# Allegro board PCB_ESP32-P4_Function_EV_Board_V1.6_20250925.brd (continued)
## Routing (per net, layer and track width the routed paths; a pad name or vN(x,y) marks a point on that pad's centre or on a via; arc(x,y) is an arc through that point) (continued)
GND_EARTH: length 183
  TOP w0.635: 35.35,6.15 J19.18 36.13,4.82 ; J18.6 16.55,11.71 ; J18.6 18.63,9.63 ; J18.6 14.47,9.63 ; J18.6 16.55,7.55 ; 29.74,4.82 J15.19 30.52,6.15 ; 20.31,1.97 J15.17 ; J15.17 21.09,3.15 ; J15.17 21.87,1.97 ; J20.17 51.17,3.15 ; J20.17 50.39,1.97 ; J20.17 51.95,1.97 ; 21.09,4.82 J15.18 20.31,6.15 ; 35.35,1.97 J19.17 ; J19.17 36.91,1.97 ; J19.17 36.13,3.15 ; 45.56,6.15 J19.19 44.78,4.82 ; 51.17,4.82 J20.18 50.39,6.15 ; 59.04,1.97 J20.20 ; J20.20 59.82,3.15 ; J20.20 60.6,1.97 ; 3.41,7.55 J18.5 ; J18.5 1.33,9.63 ; J18.5 3.41,11.71 ; J18.5 5.49,9.63 ; 44,1.97 J19.20 ; J19.20 45.56,1.97 ; J19.20 44.78,3.15 ; 60.6,6.15 J20.19 59.82,4.82 ; 28.96,1.97 J15.20 ; J15.20 30.52,1.97 ; J15.20 29.74,3.15
  GND w0.635: 44,1.97 J19.20 ; J19.20 45.56,1.97 ; J19.20 44.78,3.15 ; J15.17 21.87,1.97 ; J15.17 20.31,1.97 ; J15.17 21.09,3.15 ; J19.17 36.91,1.97 ; J19.17 35.35,1.97 ; J19.17 36.13,3.15 ; J18.5 5.49,9.63 ; J18.5 1.33,9.63 ; J18.5 3.41,7.55 ; J18.5 3.41,11.71 ; J20.17 51.95,1.97 ; J20.17 51.17,3.15 ; J20.17 50.39,1.97 ; 14.47,9.63 J18.6 ; J18.6 16.55,7.55 ; J18.6 18.63,9.63 ; J18.6 16.55,11.71 ; J20.20 59.82,3.15 ; J20.20 60.6,1.97 ; J20.20 59.04,1.97 ; 44.78,4.82 J19.19 45.56,6.15 ; 20.31,6.15 J15.18 21.09,4.82 ; 36.13,4.82 J19.18 35.35,6.15 ; 28.96,1.97 J15.20 ; J15.20 29.74,3.15 ; J15.20 30.52,1.97 ; 59.82,4.82 J20.19 60.6,6.15 ; 51.17,4.82 J20.18 50.39,6.15 ; 29.74,4.82 J15.19 30.52,6.15
  POWER w0.635: J15.20 30.52,1.97 ; J15.20 29.74,3.15 ; J15.20 28.96,1.97 ; J15.17 21.09,3.15 ; J15.17 20.31,1.97 ; J15.17 21.87,1.97 ; J18.5 3.41,11.71 ; J18.5 1.33,9.63 ; J18.5 5.49,9.63 ; J18.5 3.41,7.55 ; 59.82,4.82 J20.19 60.6,6.15 ; 59.04,1.97 J20.20 ; J20.20 60.6,1.97 ; J20.20 59.82,3.15 ; J19.17 36.91,1.97 ; J19.17 36.13,3.15 ; J19.17 35.35,1.97 ; 16.55,7.55 J18.6 ; J18.6 18.63,9.63 ; J18.6 16.55,11.71 ; J18.6 14.47,9.63 ; 45.56,6.15 J19.19 44.78,4.82 ; 50.39,1.97 J20.17 ; J20.17 51.17,3.15 ; J20.17 51.95,1.97 ; 20.31,6.15 J15.18 21.09,4.82 ; 30.52,6.15 J15.19 29.74,4.82 ; 51.17,4.82 J20.18 50.39,6.15 ; J19.20 44.78,3.15 ; J19.20 44,1.97 ; J19.20 45.56,1.97 ; 35.35,6.15 J19.18 36.13,4.82
  BOTTOM w0.635: 35.35,1.97 J19.17 ; J19.17 36.13,3.15 ; J19.17 36.91,1.97 ; 59.04,1.97 J20.20 ; J20.20 60.6,1.97 ; J20.20 59.82,3.15 ; 21.09,4.82 J15.18 20.31,6.15 ; J18.6 16.55,11.71 ; J18.6 16.55,7.55 ; J18.6 18.63,9.63 ; J18.6 14.47,9.63 ; 51.17,4.82 J20.18 50.39,6.15 ; J19.20 45.56,1.97 ; J19.20 44.78,3.15 ; J19.20 44,1.97 ; 29.74,4.82 J15.19 30.52,6.15 ; J15.17 21.09,3.15 ; J15.17 20.31,1.97 ; J15.17 21.87,1.97 ; 36.13,4.82 J19.18 35.35,6.15 ; 60.6,6.15 J20.19 59.82,4.82 ; 1.33,9.63 J18.5 ; J18.5 5.49,9.63 ; J18.5 3.41,11.71 ; J18.5 3.41,7.55 ; 50.39,1.97 J20.17 ; J20.17 51.95,1.97 ; J20.17 51.17,3.15 ; 28.96,1.97 J15.20 ; J15.20 29.74,3.15 ; J15.20 30.52,1.97 ; 44.78,4.82 J19.19 45.56,6.15
  vias: v1(0.82,11.81) v1(0.88,8.55) v1(0.92,4.63) v1(1.45,1.17) v1(3.47,6.29) v1(3.53,2.97) v1(3.94,11.86) v1(5.96,9.74) v1(6.47,4.71) v1(6.56,0.97) v1(8.63,9.17) v1(9.34,6.52) v1(9.39,2.86) v1(11.56,4.8) v1(11.65,0.9) v1(11.92,9.17) v1(13.9,6.68) v1(13.86,2.96) v1(14.14,10.02) v1(16.14,4.91) v1(16.18,0.96) v1(18.41,6.71) v1(18.37,2.97) v1(18.89,9.15) v1(20.26,0.85) v1(20.44,7.56) v1(21.1,4.44) v1(21.07,3.45) v1(22.6,3.01) v1(23.23,0.9) v1(25.33,3.03) v1(27.02,0.9) v1(28.08,3.01) v1(29.76,4.41) v1(29.76,3.45) v1(30.7,0.83) v1(30.84,6.92) v1(32.79,5.13) v1(32.82,2.59) v1(35.09,6.98) v1(35.17,0.87) v1(36.13,4.46) v1(36.13,3.4) v1(37.27,0.88) v1(37.67,3.09) v1(40.55,2.01) v1(43.5,3.01) v1(43.62,0.86) v1(44.79,4.46) v1(44.79,3.42) v1(45.65,0.88) v1(45.99,6.92) v1(47.98,5.11) v1(48,2.54) v1(50.04,6.92) v1(50.24,0.86) v1(51.18,4.44) v1(51.18,3.47) v1(52.92,3) v1(52.93,0.91) v1(55.73,2.07) v1(58.27,3.04) v1(58.32,0.91) v1(59.82,4.44) v1(59.84,3.42) v1(60.85,7.1) v1(61.01,1.93) v1(61.7,7.11) v1(61.74,3.85) v1(62.12,5.96) v1(62.96,5.91) v1(63.73,7.1) v1(63.68,3.89) v1(63.71,0.93)
GND_RJ45_EARTH: length 18.6
  TOP w1.2: R181.1 84.39,11.83 J17.SHD1 J17.SHD2
VBUS_EN: length 2.7
  TOP w0.254: R145.2 17.17,24.14 16.25,23.23 R152.2 U9.4
VBUS_OUT: length 26.5
  TOP w0.635: 5.49,12.34 J18.1 ; J18.1 6.48,13.33 ; J18.1 7.47,12.34 ; J18.1 6.48,11.35
  TOP w0.8: U9.1 18.88,20.14 18.51,19.77
  TOP w1: C75.1 C72.1 16.77,18.03 18.51,19.77
  POWER w1: v1(19.98,16.25) v1(19.27,16.25) 13.66,16.25 11.17,18.74 8.3,18.74 v1(6.57,17.01) v1(6.57,16.35)
VCC_5V: length 164.8
  TOP w0.254: v1(43.68,18.02) 43.34,18.02 C71.1 ; R226.2 53.64,39.92 52.9,39.18 51.44,39.18 v1(50.86,39.77) ; R175.2 41.22,18.48 41.21,18.48 ; R173.1 v1(49.68,14.49) ; R151.1 18.28,23.26 R145.1 18.28,24.52 v1(18.03,24.78)
  TOP w0.508: U5.1 50.83,41.88 C48.1 50.84,40.59 C49.1 v1(50.86,39.77)
  TOP w0.8: 57.74,41.71 58.03,42 v1(58.03,42.08) v1(57.37,42.08) 57.37,42.08 57.74,41.71 ; 57.74,41.71 57.74,41.27 R171.2
  TOP w1: 14.6,19.66 15.09,20.14 U9.5
  TOP w1.5: C71.1 38.22,18.48 SW3.1
  POWER w0.254: v1(49.68,14.49) 49.23,14.04 45.43,14.04 44.57,14.9 44.57,17.14 v1(43.68,18.02)
  POWER w0.508: 55.08,38.95 55.08,38.95 51.67,38.95 v1(50.86,39.77) ; J1.4 J1.2 6.85,70.25 6.85,68.1 1.44,62.69 1.44,32.3 13.71,20.03
  POWER w0.8: 55.08,38.95 55.08,39.79 v1(57.37,42.08)
  POWER w1: 14.14,19.7 21.7,19.7 22.67,20.66 45.02,20.66 55.08,30.72 55.08,38.95
  POWER w1.5: 37.1,20.66 37.1,20.66 SW3.1
  BOTTOM w0.254: v1(18.03,24.78) 13.71,20.46 v1(13.71,20.1)
  vias: v1(13.71,19.44)
VDD_FLASH: length 16
  TOP w0.18: 18.1,45.66 18.1,45.51 18.71,44.9 18.84,44.9 18.91,44.83 U4.30
  TOP w0.381: U2.8 15.43,58.15 15.81,57.77 15.81,56.85 15.74,56.77 C16.1 R18.2 15.74,54.51 16.68,53.57 R35.2 R37.2 C20.1 C25.1 16.68,47.08 18.1,45.66
25M_XI: length 1.3
  TOP w0.127: R161.1 74.42,24.46 U8.2
25M_XO: length 1.3
  TOP w0.127: R158.1 74.45,24.86 U8.3
ADCVREF: length 14.8
  TOP w0.254: U3.15 67.82,52.2 68.21,52.59 68.21,53.13 68.57,53.48 C43.1 69.02,55.85 66.77,58.11 60.95,58.11 R73.2
BAT: length 2.3
  BOTTOM w0.381: TP2.1 30.24,49.44 R196.1
C6_EN: length 59.7
  TOP w0.127: U1.8 75.3,70.84 R4.1 C8.1 72.54,72.66 68.11,72.66 J2.1 ; v1(49.9,59.55) 44.72,59.55 38.75,53.58 38.75,43.37 R76.2
  POWER w0.127: J2.1 65.04,69.59 v1(65.04,66.87)
  BOTTOM w0.127: v1(65.04,66.87) 63.64,65.47 55.82,65.47 v1(49.9,59.55)
C6_IO8: length 1.7
  TOP w0.127: U1.22 R10.1
C6_IO9: length 10.3
  TOP w0.127: v1(73.31,65.17) 73.31,61.03 72.67,60.38 U1.23
  BOTTOM w0.127: v1(73.31,65.17) 72.49,65.99 J2.6
C6_U0RXD: length 14
  TOP w0.127: v1(76.89,59.35) 76.9,59.34 U1.30
  BOTTOM w0.127: J2.5 68.11,64.4 71.06,64.4 76.11,59.35 v1(76.89,59.35)
C6_U0TXD: length 17.3
  TOP w0.127: v1(77.7,59.86) U1.31
  BOTTOM w0.127: v1(77.7,59.86) 76.08,59.86 71.2,64.73 68.32,64.73 67.81,65.24 67.81,67.24 J2.3
C6_WAKEUP: length 59.3
  TOP w0.127: v1(77.71,68.27) 77.7,68.28 U1.5 ; v1(52.21,60.49) 34.18,60.49 29.76,56.07 R30.2
  POWER w0.127: v1(77.71,68.27) 72.38,62.93 64.47,62.93 62.28,65.12 56.84,65.12 v1(52.21,60.49)
CNN_GPIO0: length 28
  BOTTOM w0.127: R199.1 32.1,47.08 36.26,47.08 37.81,48.63 37.81,64.94 36.31,66.44 J1.23
CNN_GPIO1: length 30.9
  BOTTOM w0.127: R197.1 32.12,47.39 36.08,47.39 37.43,48.73 37.43,64.53 35.04,66.92 35.04,70.5 J1.22
CNN_GPIO2: length 16.6
  TOP w0.127: R22.1 31.48,55.71 v1(31.87,56.1)
  BOTTOM w0.127: J1.21 31.87,67.33 v1(31.87,56.1)
CNN_GPIO3: length 18.5
  TOP w0.127: R48.1 30.39,51.6 v1(30.67,51.88)
  BOTTOM w0.127: J1.19 31.38,69.08 31.38,55.69 30.67,54.98 v1(30.67,51.88)
CNN_GPIO4: length 19
  TOP w0.127: R31.1 v1(30.62,56.12)
  BOTTOM w0.127: v1(30.62,56.12) 30.39,56.35 30.39,66.75 29.96,67.19 29.96,70.5 J1.18
CNN_GPIO5: length 21.9
  TOP w0.127: R47.1 v1(29.35,51.88)
  BOTTOM w0.127: J1.16 27.42,70.5 27.42,68.62 29.4,66.64 29.4,51.93 v1(29.35,51.88)
CNN_GPIO6: length 16.8
  TOP w0.127: v1(28.89,56.17) 28.89,54.52 28.89,54.52 R29.1
  BOTTOM w0.127: J1.15 28.89,66.49 v1(28.89,56.17)
CNN_GPIO7: length 32.5
  TOP w0.127: R46.1 28.31,51.78 v1(28.44,51.91) ; v1(27.32,65.1) 15.04,65.1 J1.3
  BOTTOM w0.127: v1(27.32,65.1) 27.32,57.06 28.44,55.95 v1(28.44,51.91)
CNN_GPIO8: length 27.3
  TOP w0.127: v1(27.78,55.92) R28.1 ; v1(26.86,65.56) 17.12,65.56 J1.5
  BOTTOM w0.127: v1(26.86,65.56) 26.86,56.83 v1(27.78,55.92)
CNN_GPIO20: length 16.5
  TOP w0.127: R33.1 v1(21.48,54.27)
  BOTTOM w0.127: J1.13 21.48,67.1 v1(21.48,54.27)
CNN_GPIO21: length 18.1
  TOP w0.127: R39.1 v1(20.97,51.88)
  BOTTOM w0.127: J1.11 20.97,69.13 v1(20.97,51.88)
CNN_GPIO22: length 18.9
  TOP w0.127: R32.1 v1(20.44,54.3)
  BOTTOM w0.127: J1.12 19.8,70.5 19.8,67.29 20.44,66.65 v1(20.44,54.3)
CNN_GPIO23: length 19.7
  TOP w0.127: R38.1 v1(19.93,51.88)
  BOTTOM w0.127: J1.7 19.93,65.29 v1(19.93,51.88)
CNN_GPIO26: length 64.4
  POWER w0.127: v1(17.11,26.55) 25.99,26.55 v1(26.69,27.24)
  BOTTOM w0.127: J1.31 46.47,66.64 40.38,60.54 40.38,41.93 34.79,36.34 34.79,34.98 28.88,29.07 28.35,29.07 26.69,27.41 v1(26.69,27.24) ; v1(17.11,26.55) 18.57,26.55 19.64,27.61 19.64,28.31 R228.2
CNN_GPIO27: length 75.9
  POWER w0.127: v1(17.39,25.95) 26.09,25.95 27.33,27.19 v1(27.33,27.3)
  BOTTOM w0.127: J1.38 52.9,72.96 48.48,72.96 47.73,72.22 47.73,67.26 40.74,60.28 40.74,41.86 35.11,36.22 35.11,34.8 29.05,28.74 28.46,28.74 27.33,27.61 v1(27.33,27.3) ; v1(17.39,25.95) 18.49,25.95 19.94,27.4 19.94,28.34 R227.2
CNN_GPIO32: length 52.9
  TOP w0.127: R116.2 v1(23.13,30.8)
  BOTTOM w0.127: v1(23.13,30.8) 24.54,30.8 25.05,30.29 28.41,30.29 33.52,35.4 33.52,37.63 33.57,37.68 33.57,37.73 38.55,42.71 38.55,66.75 40.12,68.33 40.12,70.5 J1.26
CNN_GPIO33: length 53.3
  TOP w0.127: R134.2 23.64,27.67 v1(24.15,27.17)
  BOTTOM w0.127: v1(24.15,27.17) 25.95,27.17 28.18,29.4 28.74,29.4 34.46,35.12 34.46,37.38 39.61,42.54 39.61,61.18 43.93,65.49 J1.29
CNN_GPIO36: length 49.6
  TOP w0.127: R112.2 v1(25.29,30.75)
  BOTTOM w0.127: v1(25.29,30.75) 28.44,30.75 33.21,35.52 33.21,37.71 33.32,37.81 33.32,37.86 38.19,42.74 38.19,65.29 37.58,65.9 37.58,70.5 J1.24
CNN_GPIO37: length 71.1
  TOP w0.127: R136.2 26.23,28.13 v1(26.23,28.13) ; J1.8 17.29,70.47 17.29,68.15 19.37,66.07 38,66.07 38.9,65.17 v1(39.39,65.17)
  BOTTOM w0.127: v1(39.39,65.17) 39.23,65.01 39.23,42.54 34.1,37.4 34.1,35.17 28.64,29.71 27.81,29.71 v1(26.23,28.13)
CNN_GPIO38: length 68.2
  TOP w0.127: v1(26.66,29.81) 26.28,30.19 R118.2 ; J1.10 19.78,70.52 19.78,68 21.37,66.41 38.4,66.41 v1(39.04,65.76)
  BOTTOM w0.127: v1(26.66,29.81) 26.85,30 28.53,30 33.82,35.3 33.82,37.61 38.93,42.71 38.93,65.65 v1(39.04,65.76)
CNN_GPIO45: length 43.3
  BOTTOM w0.127: R100.2 42.43,36.86 42.43,58.65 51.03,67.25 53.9,67.25 55.36,68.71 55.36,70.5 J1.40
CNN_GPIO46: length 42.3
  TOP w0.127: R97.2 v1(37.84,35.73)
  BOTTOM w0.127: J1.36 50.28,70.5 50.28,68.48 41.43,59.63 41.43,41.68 39.31,39.56 39.31,37.53 38.03,36.25 38.03,35.92 v1(37.84,35.73)
CNN_GPIO47: length 40.5
  TOP w0.127: R94.2 40.69,36.26 v1(41.79,37.35)
  BOTTOM w0.127: J1.37 52.45,67.59 50.69,67.59 42.13,59.03 42.13,37.94 41.79,37.59 v1(41.79,37.35)
CNN_GPIO48: length 37.7
  TOP w0.127: R93.2 v1(37.89,36.77)
  BOTTOM w0.127: J1.33 49.01,67.91 41.09,59.98 41.09,41.74 38.87,39.51 38.87,37.75 v1(37.89,36.77)
CNN_GPIO53: length 35.2
  TOP w0.127: R85.1 40.64,39.41 v1(41.39,40.16)
  BOTTOM w0.127: v1(41.39,40.16) 41.77,40.54 41.77,59.32 51.55,69.1 J1.35
CNN_GPIO54: length 35.9
  TOP w0.127: R80.1 37.68,39.92 v1(37.94,40.17)
  BOTTOM w0.127: J1.32 45.2,70.5 45.2,66.11 40,60.9 40,42.23 v1(37.94,40.17)
CODEC_CE: length 3.1
  TOP w0.127: U3.20 64.97,53.19 63.64,54.52 R60.1 R57.2
COL: length 3.4
  TOP w0.127: U8.4 73.96,25.26 75.15,26.45 R153.1 75.64,26.98 75.64,27.18 R149.2
CRS: length 5.2
  TOP w0.127: U8.20 68.06,25.66 R155.2 66.99,25.77 65.63,25.77 65.32,26.08 65.32,26.27 R154.1
CSI_A_CLKN: length 23.5
  TOP w0.102: R86.2 16.41,39.19 14.32,39.19 12.83,37.69 12.83,36.06 13.06,35.83 14.53,35.83 14.8,35.56 14.8,34.88 14.92,34.76 15.66,34.76 15.95,34.47 15.95,34.07 15.68,33.8 14.92,33.8 14.8,33.68 14.8,33.51 14.92,33.39 15.61,33.39 15.92,33.08 15.92,32.69 15.65,32.43 14.9,32.43 14.8,32.32 14.8,31.77 14.52,31.49 14.09,31.49 13.81,31.77 13.81,34.58 13.68,34.71 13.32,34.71 13.2,34.59 13.2,33.84 12.93,33.57 12.08,33.57 11.75,33.23 J9.8
CSI_A_CLKP: length 23.5
  TOP w0.102: J9.9 11.77,34.23 12.16,33.85 12.82,33.85 12.92,33.95 12.92,34.71 13.2,34.99 13.79,34.99 14.09,34.7 14.09,31.88 14.2,31.77 14.4,31.77 14.52,31.88 14.52,32.44 14.78,32.7 15.54,32.7 15.64,32.81 15.64,32.97 15.49,33.11 14.8,33.11 14.52,33.39 14.52,33.79 14.8,34.08 15.57,34.08 15.68,34.18 15.68,34.35 15.54,34.48 14.8,34.48 14.52,34.77 14.52,35.45 14.42,35.55 12.94,35.55 12.55,35.94 12.55,37.81 14.2,39.46 16.41,39.46 R82.2
CSI_A_DATA0N: length 22.3
  TOP w0.102: J9.2 10.43,27.23 10.18,27.49 9.63,27.49 8.77,28.34 8.77,40.74 9.43,41.39 12.49,41.39 13.45,40.43 15.08,40.43 R78.2
CSI_A_DATA0P: length 22.3
  TOP w0.102: J9.3 10.48,28.23 10.02,27.77 9.74,27.77 9.61,27.89 9.61,28.06 9.49,28.19 9.32,28.19 9.05,28.46 9.05,28.64 9.22,28.82 9.22,29.01 9.05,29.18 9.05,29.38 9.25,29.58 9.25,29.78 9.05,29.98 9.05,30.21 9.25,30.41 9.25,30.62 9.05,30.82 9.05,31.11 9.25,31.31 9.25,31.51 9.05,31.71 9.05,40.62 9.54,41.11 12.37,41.11 13.33,40.15 15,40.15 15.2,39.95 R81.2
CSI_A_DATA1N: length 18.9
  TOP w0.102: v1(14.34,30.06) 14.34,30.33 14.18,30.5 12,30.5 11.74,30.23 J9.5 ; R88.2 15.08,38.53 14.75,38.53 14.33,38.12 14.33,36.96 v1(14.14,36.77)
  BOTTOM w0.102: v1(14.34,30.06) 14.34,31.96 14.22,32.08 11.46,32.08 11.18,32.36 11.18,32.76 11.46,33.04 14.22,33.04 14.34,33.16 14.34,36.57 v1(14.14,36.77)
CSI_A_DATA1P: length 18.8
  TOP w0.102: v1(14.82,36.77) 14.72,36.77 14.61,36.88 14.61,38 14.86,38.25 15,38.25 15.2,38.06 R90.2 ; J9.6 11.76,31.23 12.22,30.77 14.29,30.77 14.6,30.46 14.75,30.46 v1(14.83,30.54)
  BOTTOM w0.102: v1(14.83,30.54) 14.72,30.54 14.62,30.64 14.62,32.08 14.34,32.36 11.58,32.36 11.46,32.48 11.46,32.65 11.58,32.76 14.34,32.76 14.62,33.05 14.62,35.83 14.8,36.01 14.8,36.22 14.62,36.4 14.62,36.67 14.72,36.77 v1(14.82,36.77)
CSI_CLKN: length 2.4
  TOP w0.102: U4.45 19,39.58 18.97,39.61 18.07,39.61 17.65,39.19 17.29,39.19 R86.1
CSI_CLKP: length 2.4
  TOP w0.102: U4.44 19,39.92 18.96,39.89 17.96,39.89 17.53,39.46 17.29,39.46 R82.1
CSI_DATA0N: length 3.8
  TOP w0.102: R78.1 15.89,40.36 16.26,40.36 16.49,40.59 18.97,40.59 19.01,40.62 U4.42
CSI_DATA0P: length 3.8
  TOP w0.102: R81.1 15.89,40.09 16.38,40.09 16.6,40.31 18.98,40.31 19.01,40.27 U4.43
CSI_DATA1N: length 4
  TOP w0.102: U4.46 18.98,39.23 18.95,39.19 18.29,39.19 17.56,38.46 15.89,38.46 R88.1
CSI_DATA1P: length 4
  TOP w0.102: U4.47 18.99,38.88 18.96,38.91 18.4,38.91 17.68,38.19 15.89,38.19 R90.1
CSI_IO0: length 3.5
  TOP w0.127: J9.11 v1(9.87,36.23)
  BOTTOM w0.127: v1(9.87,36.23) 9.54,36.23 R123.2
CSI_IO1: length 3.6
  TOP w0.127: J9.12 v1(9.87,37.23)
  BOTTOM w0.127: R111.2 9.67,37.23 v1(9.87,37.23)
CSI_REXT: length 1.4
  TOP w0.18: U4.48 v1(19.93,38.52)
  BOTTOM w0.18: v1(19.93,38.52) 19.93,38.73 R203.1
DACVREF: length 2.1
  TOP w0.254: C42.2 68.9,52.57 68.13,51.8 U3.14
DSI_A_CLKN: length 24.6
  TOP w0.102: J5.5 4.8,51.5 4.32,51.98 3.97,51.98 3.85,51.85 3.85,51.72 3.72,51.59 3.59,51.59 3.47,51.48 3.47,51.25 3.69,51.04 3.69,50.8 3.47,50.59 3.47,50.34 3.67,50.15 3.67,49.9 3.47,49.7 3.47,49.51 3.67,49.31 3.67,49.04 3.47,48.85 3.47,48.62 3.69,48.4 3.69,48.23 3.47,48.01 3.47,47.34 4.11,46.7 8.88,46.7 9,46.82 9,47.78 9.28,48.06 9.68,48.06 9.96,47.78 9.96,46.82 10.08,46.7 10.96,46.7 11.23,46.44 11.23,45.98 10.87,45.63 10.87,45.46 10.99,45.34 11.16,45.34 11.51,45.69 11.91,45.69 14.88,42.72 15.03,42.72 15.2,42.89 R72.1
DSI_A_CLKP: length 24.6
  TOP w0.102: R74.1 15.06,42.44 14.77,42.44 11.8,45.41 11.63,45.41 11.28,45.06 10.88,45.06 10.59,45.34 10.59,45.74 10.95,46.1 10.95,46.32 10.85,46.42 9.96,46.42 9.68,46.7 9.68,47.66 9.56,47.78 9.39,47.78 9.28,47.66 9.28,46.7 8.99,46.42 3.99,46.42 3.2,47.22 3.2,51.59 3.86,52.26 4.51,52.26 4.75,52.5 J5.6
DSI_A_DATA0N: length 23
  TOP w0.102: v1(7.86,45.31) 8.07,45.1 8.07,44.65 8.69,44.03 11.18,44.03 13.73,41.49 16.41,41.49 R77.1 ; v1(7.25,54.66) 7.05,54.86 6.42,54.86 6.06,54.5 J5.8
  BOTTOM w0.102: v1(7.25,54.66) 7.45,54.85 7.69,54.85 8.07,54.46 8.07,45.53 v1(7.86,45.31)
DSI_A_DATA0P: length 23
  TOP w0.102: R75.1 16.41,41.76 13.84,41.76 11.29,44.31 8.8,44.31 8.35,44.76 8.35,45.12 v1(8.54,45.31) ; v1(7.25,55.34) 7.05,55.14 6.45,55.14 6.09,55.5 J5.9
  BOTTOM w0.102: v1(7.25,55.34) 7.46,55.13 7.8,55.13 8.35,54.58 8.35,45.49 8.53,45.31 v1(8.54,45.31)
DSI_A_DATA1N: length 26
  TOP w0.102: J5.2 6.04,48.5 6.4,48.86 8.78,48.86 9.19,49.27 9.19,52.92 9.32,53.05 9.49,53.05 9.6,52.94 9.6,52.3 9.88,52.01 10.88,52.01 10.99,51.91 10.99,51.74 10.86,51.61 9.88,51.61 9.6,51.32 9.6,50.92 9.88,50.64 10.83,50.64 10.95,50.52 10.95,50.35 10.83,50.23 9.88,50.23 9.6,49.95 9.6,49.21 9.96,48.85 10.51,48.85 15.92,43.44 16.41,43.44 R71.1
DSI_A_DATA1P: length 26
  TOP w0.102: J5.3 6.06,49.5 6.42,49.14 8.66,49.14 8.91,49.39 8.91,53.03 9.21,53.33 9.61,53.33 9.88,53.06 9.88,52.41 10,52.29 11,52.29 11.27,52.02 11.27,51.62 10.97,51.33 10,51.33 9.88,51.21 9.88,51.04 10,50.92 10.95,50.92 11.23,50.64 11.23,50.24 10.95,49.96 10,49.96 9.88,49.84 9.88,49.32 10.08,49.13 10.62,49.13 16.03,43.71 16.41,43.71 R69.1
DSI_CLKN: length 3.8
  TOP w0.102: R72.2 15.89,42.76 17.52,42.76 17.94,42.34 18.97,42.34 19.01,42.38 U4.37
DSI_CLKP: length 3.8
  TOP w0.102: R74.2 15.89,42.49 17.4,42.49 17.82,42.06 18.98,42.06 19.02,42.02 U4.38
DSI_DATA0N: length 2.3
  TOP w0.102: U4.40 18.98,41.33 18.95,41.36 17.74,41.36 17.61,41.49 17.29,41.49 R77.2
DSI_DATA0P: length 2.3
  TOP w0.102: R75.2 17.29,41.76 17.73,41.76 17.85,41.64 18.96,41.64 18.99,41.67 U4.39
DSI_DATA1N: length 2.5
  TOP w0.102: U4.36 19,42.73 18.97,42.76 18.06,42.76 17.4,43.42 17.27,43.42 R71.2
DSI_DATA1P: length 2.5
  TOP w0.102: R69.2 17.3,43.7 17.52,43.7 18.18,43.04 18.96,43.04 19,43.08 U4.35
DSI_REXT: length 1.3
  TOP w0.18: U4.34 v1(19.9,43.42)
  BOTTOM w0.18: R202.1 19.9,43.24 v1(19.9,43.42)
EN_DCDC: length 9.8
  TOP w0.127: v1(29.53,35.78) 29.28,36.03 29.28,36.63 29.44,36.79 29.44,37.01 29.33,37.12 U4.79 ; U7.1 31.11,29.51 v1(31.11,29.51)
  POWER w0.127: v1(29.53,35.78) 29.7,35.78 30.22,35.26 30.22,30.4 v1(31.11,29.51)
ESP_3V3: length 349.5
  TOP w0.18: v1(28.16,37.23) 28.23,37.16 U4.77 ; U4.75 27.52,37.2 v1(27.5,37.23) ; U4.96 v1(28.49,43.08) ; v1(28.44,44.62) 28.65,44.83 U4.101 ; 22.98,36.58 v1(22.98,37.2) ; v1(25.49,45.68) 25.77,45.97 U4.9 ; U4.21 v1(21.57,45.76)
  TOP w0.254: R60.2 v1(63.59,56.15) ; R3.1 76.73,56.23 76.68,56.18 ; 74.8,56.18 72.38,56.18 71.8,56.76 R6.1 70.65,56.87 R12.1 R11.1 R10.2 69.31,63.77 v1(69.29,63.78) ; 74.8,56.18 76.68,56.18 ; 74.8,56.18 74.77,56.21 R5.1 ; 76.68,56.18 78.15,56.18 78.71,56.74 R1.1 ; R4.2 75.69,71.47 77.34,71.47 C1.1
  TOP w0.381: R51.1 60.42,49.77 v1(59.73,50.46) ; R35.1 v1(15.66,52.57)
  TOP w0.508: 6.85,61.02 6.37,61.5 J5.15 ; 6.85,61.02 6.9,60.97 C10.1 7.69,62.26 C7.1 v1(7.68,63.16) ; 6.85,61.02 6.33,60.5 J5.14 ; J9.15 v1(9.87,40.23)
  TOP w0.635: C2.1 79.3,71.86 U1.3 ; R127.1 v1(39.42,29.91)
  POWER w0.254: v1(8.13,42.48) 8.13,41.1 5.73,38.7 v1(5.73,35.71)
  POWER w0.508: v1(8.13,42.48) 6.67,42.48 2.71,46.45 2.71,56.2 4.05,57.55 7.68,57.55 ; 7.68,57.55 7.74,57.55 ; 7.68,57.55 v1(7.68,63.16)
  POWER w0.635: v1(53.53,66.06) 53.64,66.16 63.21,66.16 65.59,63.78 v1(69.29,63.78) 70.21,63.78 v1(78.94,72.51) v1(79.6,72.51) ; J1.1 8.37,68.45 9.81,67.01 28.74,67.01 28.69,67.06 J1.17
  POWER w0.8: 7.74,57.55 12.72,52.57 v1(15.66,52.57) 21.28,46.95 21.28,46.27
  POWER w1: 28.74,67.01 51.18,67.01 52.3,65.89 53.14,65.89 ; 27.8,37.79 30.52,37.79 38.4,29.91 v1(39.42,29.91)
  POWER w1.2: v1(39.42,29.91) 43.31,26.03 46.19,26.03
  BOTTOM w0.127: Q8.2 60.23,35.75 R230.2 ; R209.2 20.69,36.74 v1(21.25,37.3)
  BOTTOM w0.254: R123.1 7.13,35.71 R111.1 ; R208.2 22.62,28.29 22.62,26.61 25.29,23.94 43.68,23.94 v1(45.66,25.92) ; R111.1 7.13,35.73 R109.1 ; R111.1 v1(5.73,35.71) ; v1(23.74,37.33) 23.74,37.44 23.27,37.91 R233.2 ; R98.1 C47.1 ; v1(63.59,56.15) 63.59,53.46 60.59,50.46 v1(59.73,50.46)
  BOTTOM w0.381: C90.1 28.52,43.04 v1(28.49,43.08) ; R198.1 26.58,47.11 25.49,46.02 v1(25.49,45.68) C83.1 C87.1 ; v1(22.98,37.2) 22.63,36.86 22.63,36.59 C97.1 ; 47.26,50.43 47.39,50.56 59.63,50.56 v1(59.73,50.46) ; Q8.2 61.74,34.93 61.74,33.23 60.77,32.26 ; v1(21.57,45.76) 21.58,45.76 C88.1 ; v1(28.44,44.62) C85.1
  BOTTOM w0.508: v1(8.13,42.48) C46.1 8.14,41.61 C47.1 9.83,40.27 v1(9.87,40.23) ; 60.77,32.26 62.25,30.79 64.6,30.79 R213.1
  BOTTOM w0.8: 47.26,38.6 49.49,38.6 55.83,32.26 60.77,32.26
  BOTTOM w1.5: v1(52.3,14.03) 53.57,15.29 53.57,19.79 47.26,26.1 47.26,59.73 53.15,65.62
  vias: v1(46.32,25.92) v1(46.98,25.9) v1(51.61,14.03) v1(51.61,13.37) v1(52.3,13.37) v1(52.82,66.06) v1(52.85,65.34) v1(53.53,65.34)
ESP_EN: length 19.4
  TOP w0.127: SW1.3 44.76,49.71 43.75,48.69 TP23.1 43.31,47.78 v1(43.32,47.77) ; C30.1 29.84,45.48 v1(29.82,45.49) 29.79,45.52 U4.103
  POWER w0.127: v1(29.82,45.49) 30.58,45.49 31.18,46.09 41.64,46.09 v1(43.32,47.77)
  BOTTOM w0.127: v1(29.82,45.49) 29.76,45.56 R200.2
ESP_I2C_SCL: length 100.2
  TOP w0.127: v1(25.26,60.57) 22.42,63.41 12.67,63.41 10.89,61.64 10.89,59.07 v1(9.31,57.5) 9.31,57.49 R9.1 ; v1(61.18,53.56) R52.1
  POWER w0.127: v1(25.26,60.57) 25.57,60.87 41.14,60.87 50.38,51.63 59.25,51.63 v1(61.18,53.56)
  BOTTOM w0.127: R190.1 25.51,53.61 24.83,54.3 24.83,60.14 v1(25.26,60.57) ; R109.2 R106.1 6.72,37.61 1.93,42.4 1.93,52.45 6.98,57.5 v1(9.31,57.5)
ESP_I2C_SDA: length 108.8
  TOP w0.127: R62.1 v1(64.48,56.15) ; v1(25.29,61.23) 22.75,63.77 12.56,63.77 10.53,61.74 10.53,59.25 9.79,58.51 v1(9.37,58.51) R8.1
  POWER w0.127: v1(64.48,56.15) 62.43,54.09 61.05,54.09 58.89,51.93 50.6,51.93 41.3,61.23 v1(25.29,61.23)
  BOTTOM w0.127: v1(9.37,58.51) 9.79,58.08 9.79,57.27 9.52,56.99 6.98,56.99 2.21,52.23 2.21,42.6 6.34,38.47 R101.1 R98.2 ; R194.1 25,51.2 24.5,51.7 24.5,60.44 v1(25.29,61.23)
ESP_LDO_VO1: length 33.5
  TOP w0.18: U4.71 26.12,34.79
  TOP w0.254: v1(27.96,33.21) 27.68,33.49 26.89,33.49 26.12,34.26 26.12,34.79
  TOP w0.381: R37.1 v1(15.66,50.23)
  POWER w0.381: v1(15.66,50.23) 16.14,49.75 16.14,37.58 19.22,34.51 22.29,34.51 22.5,34.31 23.13,34.31 23.33,34.51 24.88,34.51 25.85,33.54 27.63,33.54 v1(27.96,33.21)
  BOTTOM w0.254: C56.1 28.03,33.29 v1(27.96,33.21) 27.68,33.49 TP26.1
ESP_LDO_VO2: length 12.9
  TOP w0.18: 26.48,36.58 26.48,35.08 ; U4.59 21.93,37.24 v1(21.94,37.25) ; U4.67 24.73,37.13 v1(24.6,37.25)
  TOP w0.254: 26.48,35.08 26.74,34.81 v1(26.74,34.38)
  POWER w0.254: v1(21.94,37.25) 22.52,36.67 24.02,36.67 v1(24.6,37.25)
  BOTTOM w0.254: v1(26.74,34.38) 26.61,34.38 26.28,34.71 C50.1 ; C105.1 21.58,36.62 21.94,36.97 v1(21.94,37.25) ; C50.1 25.82,34.79 24.53,36.08 24.53,37.18 v1(24.6,37.25) ; C50.1 TP24.1
ESP_LDO_VO3: length 16
  TOP w0.18: U4.73 26.82,35.44 ; U4.41 v1(19.9,40.98)
  TOP w0.254: v1(27.42,34.61) 27.42,34.84 26.82,35.44
  BOTTOM w0.254: v1(19.9,40.98) 20.1,40.78 C93.1 C92.1 C91.1 23.03,40.78 24.22,39.59 24.55,39.59 24.92,39.21 24.92,37.8 25.16,37.56 25.16,36.11 25.47,35.8 26.08,35.8 26.73,36.46 C55.1 26.86,35.27 TP27.1 26.86,35.17 v1(27.42,34.61)
ESP_LDO_VO4: length 60.9
  TOP w0.18: U4.85 29.58,39.23 ; U4.74 27.18,35.85 27.24,35.79 27.24,35.74
  TOP w0.254: v1(68.29,37.25) 68.02,37.52 64.57,37.52 64.24,37.19 56.76,37.19 56.33,37.62 v1(52.44,37.62) ; 29.58,39.23 v1(29.96,39.23)
  TOP w0.381: 27.24,35.74 28.07,34.9 28.07,34.32 v1(28.06,34.31)
  POWER w0.254: v1(29.96,39.23) 30.28,39.54 32.15,39.54 32.78,38.9 50.44,38.9 51.72,37.62 v1(52.44,37.62) ; v1(65.47,32.15) 65.47,34.43 v1(68.29,37.25)
  BOTTOM w0.254: v1(68.29,37.25) 68.29,37.29 68.69,37.69 R34.1 R36.1 ; R17.1 R19.1 R21.1 v1(65.47,32.15)
  BOTTOM w0.508: v1(29.96,39.23) 30.09,39.1 C101.1 C102.1 30.09,37.13 30.39,36.82 30.39,34.61 C51.1 TP25.1 v1(28.06,34.31)
ESP_VBAT: length 5.1
  TOP w0.18: U4.102 28.54,45.17 v1(28.44,45.28)
  BOTTOM w0.254: C82.1 28.64,46.19 R200.1
  BOTTOM w0.381: v1(28.44,45.28) C84.1 C82.1 R198.2 R196.2
ESP_VDD_HP: length 47.4
  TOP w0.18: v1(20,45.73) 19.82,45.9 U4.26 ; U4.91 v1(28.49,41.33) ; U4.76 v1(27.88,35.93)
  TOP w0.508: C53.1 R128.1 v1(28.78,28.16)
  TOP w0.635: L1.2 34.68,27.28 C61.1 33.15,26.97 32.72,26.54 29.74,26.54 v1(28.8,27.48) 28.78,27.5 v1(28.78,28.16)
  POWER w0.381: v1(27.88,35.93) 21.59,35.93 20.56,36.96 v1(20.56,37.3)
  POWER w0.635: v1(27.88,35.93) 27.88,35.87 29.18,34.57 29.18,28.65 28.78,28.26
  BOTTOM w0.254: 19.33,36.86 R232.2
  BOTTOM w0.3: v1(28.49,41.33) 28.51,41.33 C94.1 29.09,40.62 29.09,36.77 28.25,35.93 v1(27.88,35.93)
  BOTTOM w0.381: C107.1 27.88,35.93 v1(27.88,35.93) ; v1(20.56,37.3) 20.12,36.86 19.33,36.86 18.89,37.3 18.89,43.3 19.52,43.93 C89.1 C86.1 19.52,45.25 v1(20,45.73)
FB_DCDC: length 9.2
  TOP w0.18: U4.78 28.57,36.2
  TOP w0.254: U7.5 31.11,31.29 30.83,31.57 30.1,31.57 29.95,31.42 C53.2 ; C53.2 29.8,33.86 28.97,34.69 28.97,35.8 28.57,36.2 ; C53.2 R128.2 R138.1
FLASH_CK: length 8.8
  TOP w0.127: U4.32 18.85,44.12 18.66,44.31 18.51,44.31 17.41,45.41 16.45,45.41 14.24,47.62 R49.2
FLASH_CK_A: length 12.2
  TOP w0.127: U2.6 13.17,60.69 12.51,60.04 12.51,57.32 14.24,55.59 R49.1
FLASH_CS: length 2.4
  TOP w0.127: R56.2 18.99,47.96 18.99,45.95 19.07,45.88 U4.27
FLASH_CS_A: length 12.8
  TOP w0.127: v1(18.94,51.78) 18.94,49.02 R56.1 ; v1(16.88,54.42) 16.75,54.55 R18.1 17.35,55.18 20.32,58.15 U2.1
  BOTTOM w0.127: v1(16.88,54.42) 18.94,52.37 v1(18.94,51.78)
FLASH_D: length 7.5
  TOP w0.127: R53.2 13.73,47.67 16.25,45.15 17.3,45.15 18.39,44.06 18.53,44.06 18.82,43.77 U4.33
FLASH_D_A: length 15.7
  TOP w0.127: R53.1 13.73,55.36 12,57.09 12,60.44 12,60.44 12,60.81 12,60.94 13.03,61.96 U2.5
FLASH_HD: length 6.3
  TOP w0.127: U4.31 18.87,44.48 18.78,44.57 18.62,44.57 17.53,45.66 16.6,45.66 14.75,47.51 R54.2
FLASH_HD_A: length 12.7
  TOP w0.127: R54.1 14.75,55.79 13,57.55 13,59.2 13.22,59.42 U2.7
FLASH_Q: length 5
  TOP w0.127: U4.28 18.93,45.52 18.74,45.72 18.74,46.02 18.43,46.32 R50.2
FLASH_Q_A: length 12.7
  TOP w0.127: v1(22.3,56.32) 21.14,55.16 19.8,55.16 18.43,53.78 R50.1 ; v1(22.89,59.43) 21.3,59.43 U2.2
  BOTTOM w0.127: v1(22.89,59.43) 22.89,56.91 v1(22.3,56.32)
FLASH_WP: length 3.6
  TOP w0.127: R55.2 18.08,47.81 18.08,46.27 18.48,45.86 18.48,45.6 18.9,45.17 U4.29
FLASH_WP_A: length 16.7
  TOP w0.127: U2.3 21.32,60.66 22.65,60.66 23.51,59.79 23.51,57.86 22.47,56.82 22.08,56.82 20.81,55.55 19.56,55.55 17.89,53.89 R55.1
GPIO0: length 3.1
  TOP w0.127: R61.1 30.78,46.78 v1(30.19,46.78) 29.62,46.78 29.47,46.62 29.47,45.99 29.35,45.88 U4.104
  BOTTOM w0.127: R61.1 30.22,46.8 v1(30.19,46.78)
GPIO1: length 3.6
  TOP w0.127: U4.1 28.57,46.74 28.95,47.11 29.86,47.11 v1(30.19,47.44) 30.45,47.69 R59.1
  BOTTOM w0.127: R59.1 30.45,47.69 v1(30.19,47.44)
GPIO2: length 7.5
  TOP w0.127: U4.2 28.23,46.97 30.93,49.67 30.93,51.43 31.48,51.98 R22.2
GPIO3: length 4.8
  TOP w0.127: U4.3 27.88,47.05 30.39,49.57 R48.2
GPIO4: length 7.5
  TOP w0.127: U4.4 27.52,47.13 29.86,49.47 29.86,51.83 R31.2
GPIO5: length 4.7
  TOP w0.127: R47.2 29.35,49.6 27.18,47.42 U4.5
GPIO6: length 7.9
  TOP w0.127: R30.1 R29.2 28.89,49.51 26.82,47.45 U4.6
GPIO7: length 5.1
  TOP w0.127: R46.2 v1(28.31,49.6) 26.48,47.76 26.48,46.42
  BOTTOM w0.127: R194.2 28.31,49.6 v1(28.31,49.6)
GPIO8: length 7.4
  TOP w0.127: R28.2 v1(27.78,52.01) 27.78,49.67 26.12,48.02 U4.8
  BOTTOM w0.127: R28.2 v1(27.78,52.01)
GPIO9: length 4.5
  TOP w0.127: U4.10 25.43,47.83 27.27,49.67 R45.2
GPIO10: length 6.9
  TOP w0.127: R27.2 26.74,49.67 25.07,48.01 U4.11
GPIO11: length 4.4
  TOP w0.127: U4.12 24.73,48.19 26.23,49.7 R44.2
GPIO12: length 6.7
  TOP w0.127: R26.2 25.69,49.65 24.38,48.33 U4.13
GPIO13: length 4.2
  TOP w0.127: U4.14 24.02,48.51 25.19,49.67 R43.2
GPIO14: length 6.6
  TOP w0.127: R25.2 24.65,49.7 23.68,48.72 U4.15
GPIO15: length 4.1
  TOP w0.127: R42.2 24.15,49.72 23.32,48.9 U4.16
GPIO16: length 6.4
  TOP w0.127: R24.2 23.61,49.72 22.98,49.09 22.98,46.42
GPIO17: length 4
  TOP w0.127: U4.18 22.62,49.32 23.1,49.8 R41.2
GPIO18: length 6.3
  TOP w0.127: U4.19 22.27,49.58 22.62,49.93 R23.2
GPIO19: length 3.8
  TOP w0.127: U4.20 21.93,50.1 R40.2
GPIO20: length 6.3
  TOP w0.127: U4.22 21.23,49.14 21.48,49.39 R33.2
GPIO21: length 3.8
  TOP w0.127: U4.23 20.88,49.48 20.97,49.57 R39.2
GPIO22: length 6.2
  TOP w0.127: U4.24 20.52,46.88 20.44,46.97 R32.2
GPIO23: length 3.9
  TOP w0.127: R38.2 20.18,49.94 20.18,46.42
GPIO24: length 3.2
  TOP w0.127: U4.52 19.08,37.12 19,37.05 19,35.91 18.38,35.28 18.38,34.69 R104.1
GPIO25: length 3.2
  TOP w0.127: U4.53 19.82,36.41 19.75,36.34 19.43,36.34 19.31,36.21 19.31,35.77 19.39,35.68 19.39,35.5 19.24,35.36 18.89,35.36 18.7,35.17 18.7,34.85 19.04,34.51 R105.1
GPIO26: length 8.3
  TOP w0.127: U4.55 20.52,35.99 20.55,35.97 20.55,33.75 19.93,33.14 19.93,31.79 19.62,31.49 19.62,30.51 v1(19.43,30.31) 19.62,30.12 19.62,29.89 R113.1
  BOTTOM w0.127: v1(19.43,30.31) 19.35,30.23 R228.1
GPIO27: length 8.3
  TOP w0.127: R131.1 19.93,29.91 19.93,30.12 v1(20.12,30.31) 19.93,30.51 19.93,31.36 20.23,31.66 20.23,33.01 20.85,33.63 20.85,35.97 20.88,35.99 U4.56
  BOTTOM w0.127: v1(20.12,30.31) 20.21,30.23 R227.1
GPIO28: length 4.3
  TOP w0.127: R114.1 21.23,32.48 U4.57
GPIO29: length 6.9
  TOP w0.127: U4.58 21.57,29.66 R132.1
GPIO30: length 4.4
  TOP w0.127: U4.60 22.27,36.12 21.94,35.78 21.94,32.49 R115.1
GPIO31: length 7.2
  TOP w0.127: U4.61 22.62,36.04 22.27,35.68 22.27,33.09 22.6,32.75 R133.1
GPIO32: length 4.3
  TOP w0.127: R116.1 23.13,33.01 23.32,33.2 U4.63
GPIO33: length 7
  TOP w0.127: U4.64 23.68,35.94 23.61,35.88 23.61,29.67 R134.1
GPIO34: length 5.1
  TOP w0.127: R117.1 v1(24.18,32.94) 24.18,33.17 23.89,33.45 23.89,35.75 24.02,35.89 U4.65
  BOTTOM w0.127: v1(24.18,32.94) 24.2,32.92 R205.2
GPIO34_BOOTMODE: length 1.2
  BOTTOM w0.127: 24.2,31.28 23.69,31.28 TP34.1
GPIO35: length 9
  TOP w0.127: U4.66 24.38,35.8 24.15,35.58 24.15,33.75 24.71,33.18 v1(24.71,29.84) R135.1
  BOTTOM w0.127: R207.1 24.07,29.84 v1(24.71,29.84)
GPIO35_BOOTMODE: length 44.2
  TOP w0.127: C44.1 TP22.1 ; C44.1 43.14,40.92 v1(43.37,40.68) ; C44.1 44.01,41.34 44.76,40.59 SW2.3
  BOTTOM w0.127: v1(43.37,40.68) 45.35,38.7 45.35,29.68 40.59,24.92 25.58,24.92 23.7,26.8 23.7,28.32 R207.2 23.64,28.44 22.72,29.35 R208.1
GPIO36: length 6.3
  TOP w0.127: R112.1 v1(25.29,32.96) 25.29,33.59 25.07,33.81 U4.68
  BOTTOM w0.127: v1(25.29,32.96) 24.91,32.96 24.14,33.72 R204.1
GPIO36_BOOTMODE: length 2.2
  BOTTOM w0.127: TP33.1 21.28,33.29 R209.1 22.15,33.72 22.16,33.72 R204.2
GPIO37: length 8.5
  TOP w0.127: R136.1 25.58,29.64 v1(25.78,29.84) 25.78,33.56 25.43,33.92 U4.69
  BOTTOM w0.127: R212.1 25.77,29.83 v1(25.78,29.84)
GPIO37_BOOTMODE: length 1.1
  BOTTOM w0.127: R212.2 TP36.1
GPIO38: length 5.5
  TOP w0.127: R118.1 v1(26.28,32.94) 26.28,33.51 25.77,34.02 U4.70
  BOTTOM w0.127: R206.1 26.19,32.94 v1(26.28,32.94)
GPIO38_BOOTMODE: length 1.2
  BOTTOM w0.127: TP35.1 27.07,31.69 R206.2
GPIO39: length 9.5
  TOP w0.127: U4.80 29.66,37.48 34.94,32.2 35.68,32.2 R122.1
GPIO40: length 9.2
  TOP w0.127: U4.81 29.75,37.83 34.97,32.6 R110.1
GPIO41: length 11.7
  TOP w0.127: R108.1 34.84,33.11 29.78,38.17 U4.82
GPIO42: length 9.1
  TOP w0.127: R107.1 34.69,33.65 29.86,38.47 29.58,38.47 29.53,38.52 U4.83
GPIO43: length 11.5
  TOP w0.127: R103.1 34.56,34.18 29.99,38.75 29.68,38.75 29.56,38.88 U4.84
GPIO44: length 9.7
  TOP w0.127: U4.86 29.57,39.58 29.68,39.69 30.22,39.69 30.45,39.46 30.45,38.67 34.43,34.69 R102.1
GPIO45: length 16.2
  TOP w0.127: U4.87 29.54,39.92 29.61,40 30.65,40 35.42,35.22 40.64,35.22 v1(41.29,35.87) 41.62,35.87 R231.1
  BOTTOM w0.127: v1(41.29,35.87) 41.62,35.87 R231.1
GPIO46: length 9
  TOP w0.127: U4.88 30.75,40.27 35.3,35.73 R97.1
GPIO47: length 11.4
  TOP w0.127: U4.89 30.78,40.62 35.14,36.26 R94.1
GPIO48: length 8.8
  TOP w0.127: U4.90 30.81,40.98 35.02,36.77 R93.1
GPIO49: length 11.4
  TOP w0.127: U4.92 29.58,41.67 30.01,41.24 30.93,41.24 34.86,37.3 R92.1
GPIO50: length 8.8
  TOP w0.127: R91.1 34.71,37.84 31.05,41.49 30.14,41.49 29.61,42.02 U4.93
GPIO51: length 11.3
  TOP w0.127: U4.94 29.64,42.38 30.27,41.75 31.21,41.75 34.59,38.37 R89.1
GPIO52: length 8.7
  TOP w0.127: R87.1 34.46,38.9 31.36,42 30.47,42 29.75,42.73 U4.95
GPIO53: length 12.2
  TOP w0.127: U4.97 29.45,43.42 30.62,42.26 31.51,42.26 34.36,39.41 R85.2 R79.1
GPIO54: length 10.1
  TOP w0.127: R76.1 37.18,40.83 36.26,39.92 R80.2 34.23,39.92 31.64,42.51 30.78,42.51 29.51,43.77 U4.98
I2S_ASDOUT: length 44.5
  TOP w0.127: v1(65.32,49.06) 65.37,49.12 U3.7 ; R44.1 v1(26.23,51.88)
  POWER w0.127: v1(65.32,49.06) 65.32,48.42 65.07,48.17 49.14,48.17 43.5,53.81 28.16,53.81 v1(26.23,51.88)
I2S_DSDIN: length 44.4
  TOP w0.127: U3.9 66.17,49.12 v1(66.23,49.06) ; R45.1 27.27,51.68 v1(27.18,51.77)
  POWER w0.127: v1(66.23,49.06) 66.23,48.88 65.17,47.82 48.81,47.82 43.25,53.38 28.31,53.38 27.18,52.25 v1(27.18,51.77)
I2S_LRCK: length 43.6
  TOP w0.127: U3.8 65.77,48.43 C29.1 65.04,48.41 v1(64.81,48.63) ; R27.1 v1(26.74,54.24)
  POWER w0.127: v1(26.74,54.24) 43.73,54.24 49.34,48.63 v1(64.81,48.63)
I2S_MCLK: length 46.4
  TOP w0.127: R43.1 v1(25.19,51.88) ; C23.1 63.37,51.76 v1(63.41,51.8) U3.2
  POWER w0.127: v1(25.19,51.88) 25.19,54.19 26.08,55.08 44.29,55.08 49.98,49.39 61,49.39 v1(63.41,51.8)
I2S_SCLK: length 43.9
  TOP w0.127: U3.6 64.97,49.58 64.33,48.94 64.33,48.6 C26.1 63.82,48.72 v1(63.82,49.11) ; R26.1 25.69,53.99 v1(25.95,54.24)
  POWER w0.127: v1(25.95,54.24) 26.41,54.7 43.98,54.7 49.7,48.99 63.69,48.99 v1(63.82,49.11)
MDC: length 56.5
  TOP w0.127: v1(63.71,29.4) 63.55,29.56 45.15,29.56 39.92,24.32 25.82,24.32 22.6,27.54 R133.2 ; U8.22 68.05,24.86 R160.2 67.02,23.84 65.61,23.84 64.99,24.46 v1(64.99,24.7)
  POWER w0.127: v1(64.99,24.7) 64.99,28.29 63.87,29.4 v1(63.71,29.4)
MDIO: length 44.4
  TOP w0.127: v1(53.43,25.36) 55.11,25.36 55.71,25.96 62.58,25.96 65.66,22.87 66.99,22.87 R163.2 68.58,24.46 U8.23 ; R87.2 42.5,38.9 43.79,37.61 48.63,37.61 v1(49.09,37.15)
  BOTTOM w0.127: v1(49.09,37.15) 49.5,36.74 49.5,29.3 v1(53.43,25.36)
MICN: length 11.8
  TOP w0.127: R64.2 R65.1 60.82,55.49 62.76,57.43 66.3,57.43 67.22,56.51 67.22,55.79 C34.1
MICP: length 17.4
  TOP w0.127: 56.66,54.47 TP11.1 ; 56.66,54.47 v1(56.02,54.47) ; 56.66,54.47 57.16,54.98 60.8,54.98 62.92,57.1 66.14,57.1 66.89,56.36 66.89,55.87 C32.1
  POWER w0.127: v1(56.02,54.47) 54.68,55.81 v1(53.62,55.81)
OUTN: length 18.2
  TOP w0.254: v1(60.49,43.57) C58.1 C57.1 ; R84.2 v1(72.61,50.76)
  POWER w0.254: v1(60.49,43.57) 60.7,43.78 64.62,43.78 66.53,45.68 69.22,45.68 72.61,49.07 v1(72.61,50.76)
OUTP: length 15.8
  TOP w0.254: v1(72,49.24) 72.02,49.26 R83.2 ; v1(60.49,44.44) C59.1 C60.1
  POWER w0.254: v1(72,49.24) 68.92,46.17 66.25,46.17 64.34,44.26 60.66,44.26 v1(60.49,44.44)
PA_CTRL: length 29.2
  TOP w0.127: U10.1 65.04,45.61 64.66,45.99 v1(64.66,46.09) 64.51,46.24 R148.1 ; v1(40.73,40.3) R79.2
  POWER w0.127: v1(40.73,40.3) 46.14,45.71 64.28,45.71 v1(64.66,46.09)
PA_INL+: length 1.7
  TOP w0.254: U10.3 64.22,44.31 R147.2
PA_INL-: length 1.6
  TOP w0.254: R146.2 64.19,43.66 U10.4
PA_OUTL+: length 2
  TOP w0.381: 71.08,45.61 U10.8
  TOP w0.635: L3.2 71.68,45.61 71.08,45.61
PA_OUTL-: length 2
  TOP w0.381: 71.02,43.66 U10.5
  TOP w0.635: 71.02,43.66 71.84,43.66 L2.2
PA_PVDD1: length 15.7
  TOP w0.508: 68.77,44.31 U10.6
  TOP w0.635: 68.77,44.31 67.04,42.58 C66.1 67.04,41.22 C67.2 65.94,40.12 63.95,40.12 C63.1 61.99,39.33 58.02,39.33 R171.1
PHY_3V3: length 60.9
  TOP w0.254: v1(70.87,28.58) 71.26,28.18 U8.13 ; R155.1 v1(65.86,26.25) ; R167.1 R168.1 75.07,20.83 v1(75.4,20.51) ; v1(72.55,22.66) 72.46,22.74 U8.31 ; R160.1 v1(65.86,24.3) ; v1(66.32,21.78) 66.46,21.92 R164.1 ; v1(75.95,28.27) 75.95,28.27 R149.1 ; R157.1 v1(65.86,25.26) ; R141.1 72.39,30.09 v1(72.18,29.87) ; R163.1 v1(65.86,23.36)
  POWER w0.254: v1(66.32,21.78) 65.86,22.24 v1(65.86,23.36) v1(65.86,24.3) v1(65.86,25.26) v1(65.86,26.25)
  BOTTOM w0.254: R213.2 67.84,29.06 65.86,27.08 v1(65.86,26.25) ; J17.12 76.5,7.54 76.5,10.7 79.77,13.97 79.77,17.9 78.27,19.4 76.51,19.4 v1(75.4,20.51) 75.4,21.28 74.41,22.27 C114.1 ; v1(75.95,28.27) 73.31,28.27 ; v1(72.18,29.87) 72.18,29.41
  BOTTOM w0.381: v1(70.87,28.58) 70.6,28.84 C109.1 70.84,29.41 72.88,29.41 73.31,28.98 73.31,27.71 72.94,27.35 72.94,24.22 74.15,23.01 74.15,22.57 C114.1 73.18,22.3 C112.1 73.07,22.31 72.72,22.66 v1(72.55,22.66)
  BOTTOM w0.508: R213.2 69.34,29.2 C108.1 70.59,29.18 C109.1
PHY_AD0: length 18.6
  TOP w0.254: R141.2 72.46,28.75 v1(72.46,28.51) 72.35,28.41 72.35,28.23 72.06,27.94 U8.11
  BOTTOM w0.254: v1(72.46,28.51) 72.46,27.98 71.55,27.08 68.28,27.08 67.64,26.44 67.64,18.52 67.18,18.05 R222.2
PHY_AD3: length 34.1
  TOP w0.254: R140.2 71.81,28.73 v1(71.81,28.42) 71.66,28.28 U8.12
  BOTTOM w0.254: J17.9 70.25,7.22 70.25,9.92 65.6,14.57 65.6,17.36 67.19,18.95 67.19,26.7 68.05,27.56 71.3,27.56 71.81,28.07 v1(71.81,28.42)
PHY_ISET: length 1.6
  TOP w0.127: U8.25 70.06,22.87 69.61,22.42 R165.1
PHY_RSTN: length 49.5
  TOP w0.127: U8.32 72.86,23.18 73.08,22.96 v1(73.33,22.96) 73.34,22.95 R166.1 R167.2 ; v1(48.96,36.52) 48.38,37.1 43.72,37.1 42.45,38.37 R89.2
  POWER w0.127: v1(73.33,22.96) 73.03,23.27 70.69,23.27 68.41,20.98 65.95,20.98 65.22,21.72 65.22,22.72 63.17,24.77 53.52,24.77 v1(53.33,24.58)
  BOTTOM w0.127: v1(53.33,24.58) 48.96,28.95 v1(48.96,36.52)
PHY_TESTON: length 2.7
  TOP w0.127: R164.2 69.15,24.06 U8.24
RD+: length 13.9
  TOP w0.102: v1(69.86,19.29) 70.06,19.49 70.37,19.49 70.69,19.81 70.69,22.51 70.8,22.62 70.8,23.05 70.86,23.11 U8.27
  BOTTOM w0.102: J17.3 71.94,15.13 74.03,17.22 74.03,18.34 72.91,19.46 70.03,19.46 v1(69.86,19.29)
RD-: length 13.8
  TOP w0.102: U8.26 70.46,23.11 70.52,23.05 70.52,22.73 70.41,22.62 70.41,19.93 70.25,19.77 70,19.77 69.86,19.91 v1(69.86,19.97)
  BOTTOM w0.102: v1(69.86,19.97) 69.86,19.91 70.03,19.74 73.03,19.74 74.31,18.46 74.31,16.78 74.63,16.46 75.49,16.46 75.63,16.6 75.63,17.47 J17.6
RMII_CLK: length 52.5
  TOP w0.127: v1(44.21,30.09) 44.39,30.27 70.12,30.27 R139.1 70.3,30.79 70.72,31.21 72.74,31.21 73.45,30.5 73.45,30.28 R142.1 ; R91.2 v1(37.86,37.84)
  BOTTOM w0.127: v1(44.21,30.09) 41.47,30.09 40.87,30.68 40.87,30.89 41.37,31.4 41.37,31.59 41.23,31.74 41,31.74 40.51,31.25 40.3,31.25 40.15,31.4 40.15,31.61 40.64,32.1 40.64,32.29 40.49,32.44 40.26,32.44 39.8,31.97 39.59,31.97 39.44,32.12 39.44,32.33 39.92,32.82 39.92,33.01 39.78,33.15 39.54,33.15 39.08,32.69 38.87,32.69 38.72,32.84 38.72,33.05 39.19,33.53 39.19,33.74 39.04,33.89 38.83,33.89 38.36,33.41 38.15,33.41 38,33.56 38,33.77 38.47,34.24 38.47,34.45 38.33,34.6 38.12,34.6 37.64,34.13 37.43,34.13 37,34.56 37,37.12 37.71,37.84 v1(37.86,37.84)
RMII_RXD0: length 56.8
  TOP w0.127: R132.2 21.59,27.42 25.59,23.41 40.63,23.41 44.92,27.7 50.68,27.7 51.46,28.49 52.41,28.49 52.56,28.34 52.56,27.98 52.71,27.83 52.92,27.83 53.07,27.98 53.07,28.34 53.22,28.49 53.43,28.49 53.57,28.34 53.57,27.98 53.72,27.83 53.93,27.83 54.08,27.98 54.08,28.34 54.23,28.49 54.44,28.49 54.59,28.34 54.59,27.98 54.74,27.83 54.95,27.83 55.1,27.98 55.1,28.34 55.25,28.49 55.46,28.49 55.61,28.34 55.61,27.98 55.76,27.83 55.97,27.83 56.11,27.98 56.11,28.34 56.26,28.49 56.47,28.49 56.62,28.34 56.62,27.98 56.77,27.83 56.98,27.83 57.13,27.98 57.13,28.34 57.28,28.49 57.49,28.49 57.64,28.34 57.64,27.98 57.79,27.83 58,27.83 58.15,27.98 58.15,28.34 58.3,28.49 58.51,28.49 58.65,28.34 58.65,27.98 58.8,27.83 59.01,27.83 59.16,27.98 59.16,28.34 59.31,28.49 60.32,28.49 60.65,28.16 R144.1
RMII_RXD1: length 59.1
  TOP w0.127: R143.1 64.43,29 64.27,28.83 63.26,28.83 63.1,29 50.59,29 50.44,28.85 50.44,28.26 50.3,28.11 50.08,28.11 49.94,28.26 49.94,28.85 49.79,29 49.58,29 49.43,28.85 49.43,28.26 49.28,28.11 49.07,28.11 48.92,28.26 48.92,28.85 48.77,29 48.56,29 48.41,28.85 48.41,28.26 48.26,28.11 48.05,28.11 47.9,28.26 47.9,28.85 47.76,29 47.54,29 47.4,28.85 47.4,28.26 47.25,28.11 47.04,28.11 46.89,28.26 46.89,28.85 46.74,29 46.53,29 46.38,28.85 46.38,28.26 46.23,28.11 46.02,28.11 45.87,28.26 45.87,28.85 45.72,28.99 45.43,28.99 40.33,23.89 25.7,23.89 22.09,27.49 R115.2
RMII_RXDV: length 59.7
  TOP w0.127: R114.2 21.12,31.27 21.12,27.32 25.47,22.98 40.94,22.98 45.19,27.23 49.06,27.23 49.21,27.08 49.21,26.64 49.36,26.5 49.57,26.5 49.71,26.64 49.71,27.08 49.86,27.23 50.07,27.23 50.22,27.08 50.22,26.64 50.37,26.5 50.58,26.5 50.73,26.64 50.73,27.08 50.88,27.23 51.09,27.23 51.24,27.08 51.24,26.64 51.39,26.5 51.6,26.5 51.75,26.64 51.75,27.08 51.9,27.23 52.11,27.23 52.25,27.08 52.25,26.64 52.4,26.5 52.61,26.5 52.76,26.64 52.76,27.08 52.91,27.23 53.12,27.23 53.27,27.08 53.27,26.64 53.42,26.5 53.63,26.5 53.78,26.64 53.78,27.08 53.93,27.23 54.14,27.23 54.29,27.08 54.29,26.64 54.44,26.5 54.65,26.5 54.79,26.64 54.79,27.08 54.94,27.23 66.37,27.23 R150.1
RMII_TXD0: length 61.8
  TOP w0.127: R117.2 24.18,27.77 27.19,24.76 38.04,24.76 43.88,30.6 67.38,30.6 68.37,31.59 72.96,31.59 74.16,30.39 74.16,28.64 73.33,27.81 72.99,27.81 72.86,27.69 U8.9
RMII_TXD1: length 58.9
  TOP w0.127: U8.8 73.69,26.86 73.82,26.99 73.82,27.69 74.55,28.42 74.55,30.56 73.14,31.97 68.14,31.97 67.2,31.03 43.68,31.03 37.86,25.21 27.3,25.21 24.71,27.8 R135.2
RMII_TXEN: length 51.2
  TOP w0.127: U8.5 73.8,25.66 74.22,26.09 74.22,27.51 74.93,28.22 74.93,30.74 73.32,32.35 67.91,32.35 67.07,31.51 43.48,31.51 v1(43.4,31.59) ; R92.2 v1(40.4,37.3)
  BOTTOM w0.127: v1(40.4,37.3) 40.71,37 40.71,34.62 40.95,34.38 41.41,34.38 41.55,34.52 41.81,34.52 41.95,34.38 41.95,34.21 41.09,33.34 41.09,33.11 41.21,32.99 41.45,32.99 42.1,33.64 42.32,33.64 42.47,33.49 42.47,33.29 41.84,32.66 41.84,32 41.98,31.86 42.17,31.86 42.29,31.99 42.29,32.27 42.42,32.4 42.7,32.4 42.84,32.26 42.84,31.78 43.02,31.6 43.02,31.59 v1(43.4,31.59)
RXER: length 4.9
  TOP w0.127: U8.21 67.48,25.26 R157.2 66.99,24.78 65.61,24.78 65.32,25.07 65.32,25.28 R156.1
SD1_CLK: length 42.4
  TOP w0.127: R103.2 41.14,34.18 42.05,35.09 56.44,35.09 57.28,35.93 57.49,35.93 57.64,35.78 57.64,35.19 57.79,35.04 58,35.04 58.15,35.19 58.15,35.78 58.3,35.93 58.51,35.93 58.66,35.78 58.66,35.19 58.81,35.04 59.02,35.04 59.17,35.19 59.17,35.78 59.31,35.93 66.98,35.93 67.82,35.09 68.42,35.09 68.72,35.4 68.72,36.69 v1(68.81,36.78) ; TP15.1 v1(74.49,35.38)
  BOTTOM w0.127: v1(74.49,35.38) J21.5 73.03,35.38 72.61,35.8 72.27,35.8 71.64,36.43 71.64,36.77 D6.2 71.51,37.06 71.09,37.48 70.07,37.48 69.46,36.87 68.9,36.87 v1(68.81,36.78)
SD1_CMD: length 46.4
  TOP w0.127: v1(68.11,35.58) 67.35,36.34 56.48,36.34 56.33,36.19 56.33,35.64 56.19,35.49 55.98,35.49 55.83,35.64 55.83,36.19 55.68,36.34 55.47,36.34 55.32,36.19 55.32,35.64 55.17,35.49 54.96,35.49 54.81,35.64 54.81,36.19 54.66,36.34 54.45,36.34 54.3,36.19 54.3,35.64 54.15,35.49 53.94,35.49 53.79,35.64 53.79,36.19 53.65,36.34 53.33,36.34 52.53,35.54 41.81,35.54 40.96,34.69 R102.2 ; TP14.1 74.03,33.65 v1(74.49,33.18)
  BOTTOM w0.127: v1(74.49,33.18) J21.3 72.36,33.18 71.51,34.03 D4.2 71.51,34.34 71.06,34.79 69.38,34.79 68.6,35.58 v1(68.11,35.58) 67.33,34.79 R17.2
SD1_D0: length 45.3
  TOP w0.127: TP19.1 v1(74.51,37.58) ; R122.2 37.76,32.2 41.82,32.2 42.79,33.16 68.86,33.16 69.69,33.99 69.69,38.59 69.86,38.75 v1(70.3,38.75)
  BOTTOM w0.127: v1(74.51,37.58) J21.7 71.95,37.58 71.51,38.02 D11.2 71.51,38.3 71.06,38.75 v1(70.3,38.75) 70.17,38.88 R36.2
SD1_D1: length 47.8
  TOP w0.127: R110.2 41.57,32.6 42.61,33.65 68.77,33.65 69.26,34.13 69.26,39.23 70.15,40.12 v1(70.93,40.12) ; v1(74.49,38.68) 74.48,38.67 TP18.1
  BOTTOM w0.127: v1(74.49,38.68) J21.8 72.06,38.68 71.51,39.23 D10.2 71.51,39.55 v1(70.93,40.12) 69.94,40.12 R34.2
SD1_D2: length 45.9
  TOP w0.127: v1(68.57,34.12) 66.74,34.12 66.59,34.27 66.59,34.97 66.44,35.12 66.23,35.12 66.08,34.97 66.08,34.27 65.94,34.12 65.73,34.12 65.58,34.27 65.58,34.97 65.43,35.12 65.22,35.12 65.07,34.97 65.07,34.27 64.92,34.12 64.71,34.12 64.56,34.27 64.56,34.97 64.41,35.12 64.2,35.12 64.05,34.97 64.05,34.27 63.9,34.12 42.43,34.12 41.42,33.11 R108.2 ; TP17.1 v1(75.2,31.77)
  BOTTOM w0.127: v1(75.2,31.77) 74.42,30.98 J21.1 72.58,30.98 71.87,31.69 D8.2 71.51,31.88 71.09,32.3 70.39,32.3 v1(68.57,34.12) 68.39,33.94 68.39,33.21 R21.2
SD1_D3: length 47.3
  TOP w0.127: R107.2 41.27,33.65 42.23,34.61 59.21,34.61 60.14,35.54 60.46,35.54 60.61,35.39 60.61,34.76 60.75,34.61 60.96,34.61 61.11,34.76 61.11,35.39 61.26,35.54 61.47,35.54 61.62,35.39 61.62,34.76 61.77,34.61 61.98,34.61 62.13,34.76 62.13,35.39 62.28,35.54 62.49,35.54 62.64,35.39 62.64,34.76 62.79,34.61 63,34.61 63.15,34.76 63.15,35.39 63.29,35.54 66.75,35.54 67.69,34.61 v1(68.01,34.61) ; v1(74.72,32.38) 74.77,32.38 TP16.1
  BOTTOM w0.127: R19.2 68.01,33.72 v1(68.01,34.61) 68.9,34.61 69.94,33.57 71.04,33.57 71.51,33.1 D7.2 71.51,32.79 72.22,32.08 J21.2 74.42,32.08 v1(74.72,32.38)
SD1_VDD: length 13.9
  BOTTOM w0.127: 67.55,36.19 67.83,36.46 R16.1
  BOTTOM w0.381: J21.4 72.48,34.28 71.51,35.25 D3.2 71.51,35.73 71.05,36.19 67.55,36.19 C14.1 66.45,35.08 C15.1 65.89,35.14 TP13.1 Q8.3
SD2_CLK: length 61.8
  TOP w0.127: U1.25 72.9,57.84 72.64,57.58 71.57,57.58 v1(70.94,58.21) R12.2 ; R23.1 22.62,54.59 31.68,63.64 57.2,63.64 57.35,63.49 57.35,63.08 57.5,62.93 57.71,62.93 57.85,63.08 57.85,63.49 58,63.64 58.21,63.64 58.36,63.49 58.36,63.08 58.51,62.93 58.72,62.93 58.87,63.08 58.87,63.49 59.02,63.64 v1(60.37,63.64)
  BOTTOM w0.127: v1(60.37,63.64) 63.87,60.14 68.7,60.14 70.62,58.21 v1(70.94,58.21) 70.93,58.21 TP5.1
SD2_CMD: length 64.5
  TOP w0.127: U1.24 v1(70.94,59.58) R11.2 ; v1(60.91,64.06) 60.77,64.2 59.69,64.2 59.54,64.35 59.54,64.83 59.39,64.98 59.18,64.98 59.03,64.83 59.03,64.35 58.88,64.2 58.67,64.2 58.52,64.35 58.52,64.83 58.37,64.98 58.16,64.98 58.02,64.83 58.02,64.35 57.87,64.2 57.66,64.2 57.51,64.35 57.51,64.83 57.36,64.98 57.15,64.98 57,64.83 57,64.35 56.85,64.2 31.52,64.2 22.01,54.69 R40.1
  BOTTOM w0.127: TP4.1 71.52,59 v1(70.94,59.58) 70,60.52 64.46,60.52 v1(60.91,64.06)
SD2_D0: length 62.3
  TOP w0.127: U1.26 73.7,57.75 v1(73.59,57.64) R6.2 ; v1(65.34,61) 64.76,60.42 56.11,60.42 55.96,60.57 55.96,61.55 55.81,61.7 55.6,61.7 55.45,61.55 55.45,60.57 55.31,60.42 55.09,60.42 54.95,60.57 54.95,61.55 54.8,61.7 54.59,61.7 54.44,61.55 54.44,60.57 54.29,60.42 54.08,60.42 52.78,61.71 32.46,61.71 24.65,53.9 R25.1
  BOTTOM w0.127: TP9.1 73.27,57.32 v1(73.59,57.64) 73.59,57.89 70.48,61 v1(65.34,61)
SD2_D1: length 64.7
  TOP w0.127: R5.2 74.5,57.61 v1(74.5,57.65) U1.27 ; R42.1 24.15,54.05 32.31,62.22 55.93,62.22 57.32,60.84 59.66,60.84 59.8,60.98 59.8,61.21 59.95,61.36 60.16,61.36 60.31,61.21 60.31,60.98 60.46,60.84 60.67,60.84 60.82,60.98 60.82,61.21 60.97,61.36 61.18,61.36 61.33,61.21 61.33,60.98 61.48,60.84 61.69,60.84 61.84,60.98 61.84,61.21 61.98,61.36 62.2,61.36 62.34,61.21 62.34,60.98 62.49,60.84 62.7,60.84 62.85,60.98 62.85,61.21 63,61.36 63.21,61.36 63.36,61.21 63.36,60.98 63.51,60.84 64.11,60.84 v1(64.74,61.46)
  BOTTOM w0.127: v1(64.74,61.46) 70.7,61.46 v1(74.5,57.65) 74.49,57.64 TP8.1
SD2_D2: length 62.3
  TOP w0.127: U1.28 v1(75.3,57.63) 75.71,57.22 R3.2 ; v1(64.13,61.94) 64,61.81 59.26,61.81 59.12,61.67 59.12,61.44 58.97,61.29 58.76,61.29 58.61,61.44 58.61,61.67 58.46,61.81 58.25,61.81 58.1,61.67 58.1,61.44 57.95,61.29 57.74,61.29 57.59,61.44 57.59,61.67 57.44,61.81 57.01,61.81 56.15,62.68 32.06,62.68 23.61,54.23 R24.1
  BOTTOM w0.127: v1(64.13,61.94) 70.99,61.94 v1(75.3,57.63) 75.73,57.2 TP7.1
SD2_D3: length 65.7
  TOP w0.127: R1.2 76.93,57.63 v1(76.12,57.63) 76.1,57.64 U1.29 ; R41.1 23.1,54.37 31.87,63.13 56.43,63.13 57.12,62.45 v1(63.52,62.45)
  BOTTOM w0.127: TP6.1 76.12,57.62 v1(76.12,57.63) 71.29,62.45 v1(63.52,62.45)
SD_DET: length 8.6
  TOP w0.127: v1(74.51,39.78) 74.53,39.77 TP10.1
  BOTTOM w0.127: R16.2 69.59,40.64 D5.2 71.66,40.64 72.52,39.78 J21.9 v1(74.51,39.78)
SD_PWRN: length 19.1
  TOP w0.127: v1(56.05,36.77) 55.98,36.83 53.13,36.83 52.29,35.99 43.44,35.99 43.17,36.26 R231.2
  BOTTOM w0.127: Q8.1 60.03,34.74 R230.1 59.08,34.75 R229.2 58.07,34.75 v1(56.05,36.77)
TD+: length 10.1
  TOP w0.102: U8.30 72.06,23.12 72,23.06 72,19.28 71.77,19.05 71.77,17.17 70.48,15.88 69.55,15.88 69.43,15.84 J17.1
TD-: length 10.1
  TOP w0.102: U8.29 71.66,23.11 71.72,23.05 71.72,19.4 71.49,19.17 71.49,17.29 70.36,16.16 69.89,16.16 69.77,16.25 69.73,16.43 J17.2
TXER: length 3.5
  TOP w0.127: U8.1 73.78,24.06 73.9,23.94 73.9,23.43 R168.2 R169.1
USB0_5V: length 13.4
  TOP w0.254: J20.14 58.05,7.26 57.9,7.41 57.75,7.25 J20.13 ; J20.4 53.25,7.21 53.1,7.36 52.95,7.2 J20.3
  TOP w0.635: 57.9,7.41 v1(57.9,7.69) ; 53.1,7.36 v1(53.1,7.76)
  BOTTOM w0.254: Q3.3 47.49,10.71 47.22,10.44 Q2.1
  BOTTOM w0.635: v1(57.9,7.69) 57.17,6.95 53.91,6.95 v1(53.1,7.76)
  vias: v1(52.31,9.11) v1(52.67,9.67) v1(53,9.11)
USB1_5V: length 14
  TOP w0.254: J19.13 42.71,7.25 42.84,7.38 43.01,7.22 J19.14 ; J19.3 37.91,7.2 38.07,7.36 38.21,7.22 J19.4
  TOP w0.635: 38.07,7.36 v1(38.07,7.71) ; 42.84,7.38 v1(42.84,7.71)
  BOTTOM w0.254: 38.01,8.85 38.24,8.63 40.2,8.63 40.75,9.17 Q6.1
  BOTTOM w0.635: v1(42.84,7.71) 42.05,6.92 38.85,6.92 v1(38.07,7.71)
  vias: v1(37.61,9.08) v1(37.99,9.64) v1(38.32,9.08)
USB1P1_N: length 45.6
  TOP w0.127: v1(40.71,5.78) J19.9 40.71,7.48 40.81,7.58 40.81,7.79 D17.2 40.81,8.86 40.81,9.92 40.1,10.63 30.14,10.63 24.88,15.89 24.88,19.61 18.15,26.34 18.15,31.74 18.48,32.07 18.48,33.21 R104.2 ; J19.7 v1(39.71,5.78)
  BOTTOM w0.127: v1(39.71,5.78) v1(40.71,5.78)
USB1P1_N_2: length 56.5
  TOP w0.127: R113.2 19.64,28.35 19.64,26.78 21.09,25.33 24.83,21.58 53.23,21.58 55.31,19.5 55.31,8.8 D24.2 54.8,8.29 54.8,6.78 J20.7 v1(54.75,5.78) ; J20.9 v1(55.75,5.78)
  BOTTOM w0.127: v1(54.75,5.78) v1(55.75,5.78)
USB1P1_P: length 46.3
  TOP w0.127: J19.8 40.21,5.57 40.49,5.29 40.92,5.29 41.21,5.57 J19.10 41.21,7.48 41.11,7.57 41.11,7.79 D18.2 41.11,8.85 41.11,10.05 40.22,10.94 30.27,10.94 25.19,16.02 25.19,19.74 18.46,26.47 18.46,31.61 18.79,31.94 18.79,33.26 19.02,33.49 R105.2
USB1P1_P_2: length 57.4
  TOP w0.127: J20.8 55.25,6.72 55.25,5.44 55.45,5.24 56.01,5.24 56.25,5.47 J20.10 56.25,7.35 56.11,7.49 D23.2 55.62,8.82 55.62,19.62 53.36,21.88 24.96,21.88 19.94,26.9 19.94,28.35 R131.2
USB2_5V: length 14.8
  TOP w0.254: J15.4 23.17,7.17 23.03,7.31 22.87,7.14 J15.3 ; J15.14 27.97,7.24 27.83,7.38 27.67,7.22 J15.13
  TOP w0.635: 23.03,7.31 23.03,7.71 ; 27.83,7.38 v1(27.83,7.71)
  BOTTOM w0.254: v1(23.28,9.11) 23.33,9.06 26.76,9.06 27.22,9.52 27.22,10.84 27.06,11 Q5.1
  BOTTOM w0.635: v1(27.83,7.71) 27.07,6.95 23.84,6.95 v1(23.05,7.74)
  vias: v1(22.19,9.64) v1(22.62,9.11)
